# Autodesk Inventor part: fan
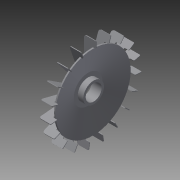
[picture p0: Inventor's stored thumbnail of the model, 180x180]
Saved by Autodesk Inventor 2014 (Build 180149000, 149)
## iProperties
Created: 2002-07
Part Number: fan
Document SubType Name: Modeling
Designer: ales
Density: 1 g/cm^3
Material: Generic
Appearance: Default
Control State: 0
Master: False
Checked Out: False
Shininess: 64.0
Length Units: 11269
Angle Units: 11279
Time Units: 11290
Mass Units: 11283
Length Display Precision: 3
Angle Display Precision: 2
Density: 0.0
Volumn: 0.0
Area: 0.0
PropertySet Name: Model Information
Author: PaulN
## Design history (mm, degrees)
sketch "Sketch1"
  geometry: L1 (0, 0)-(25, 0); L2 (25, 20)-(25, 26); L3 (25, 26)-(11.111, 26); L4 (11.111, 26)-(11.111, 36) reference; L5 (11.111, 36)-(23.519, 94.376); L6 (23.519, 94.376)-(20.585, 95); L7 (8.111, 26)-(0, 26); L8 (0, 26)-(0, 20); L9 (8.111, 26)-(8.111, 36.315); L10 (8.111, 36.315)-(20.585, 95); L11 (0, 20)-(25, 20)
  constraints: 22 end point, 5 perpendicular, 3 parallel, 2 point on line, 1 collinear, 1 horizontal, 1 vertical, 1 other
  dimensions: "d0" = 3 distance between parallel lines of L4 L9; "d1" = 25 distance between parallel lines of L8 L2; "d2" = 10 distance of L3.end L4.end; "d3" = 190 diameter of L6.end L1; "d4" = 3 distance between parallel lines of L5 L10 (= d0); "d5" = 40 diameter of L11 L1; "d6" = 6 distance of L2.start L2.end; "d7" = 12 deg angle of L10 L9
revolve "Revolution1" sketch "Sketch1" stored, may be unused: angle "d8" = 90 deg
sketch "Sketch3"
  geometry: L1 (0, 26)-(8.111, 26) reference; L2 (8.111, 36.315)-(20.585, 95) reference; L3 (8.111, -36.315)-(8.111, 36.315) reference; L4 (1.5, 26)-(1.5, 109); L5 (7.5, 115)-(29.5, 115); L6 (31.5, 113)-(31.5, 100); L7 (29.5, 98)-(22.585, 98); L8 (20.585, 96)-(20.585, 95); L9 (0, -26)-(0, 26) reference; L10 (-6.383, 0)-(38.297, 0) reference; L11 (8.111, 26)-(8.111, 36.315); A1 r 6 centre (7.5, 109) between (7.5, 115) and (1.5, 109); A2 r 2 centre (29.5, 113) between (31.5, 113) and (29.5, 115); A3 r 2 centre (29.5, 100) between (29.5, 98) and (31.5, 100); A4 r 2 centre (22.585, 96) between (22.585, 98) and (20.585, 96); 3 further points
  constraints: 12 end point, 8 point on circle, 8 tangent, 7 point on line, 4 centre point, 4 parallel, 1 collinear, 1 equal radius, 1 perpendicular
  dimensions: "d10" = 1.5 distance between parallel lines of L4 L9; "d11" = 30 distance of point (1.5, 115) point (31.5, 115); "d12" = 17 distance of point (31.5, 115) point (31.5, 98); "d13" = 230 diameter of L5 L10; "d14" = 6 radius of A1; "d15" = 2 radius of A2; "d16" = 2 radius of A4
extrude "Extrusion1" join sketch "Sketch3" stored distance "d17" = 1.5; taper "d18" = 0 deg
body "Solid1"
pattern_circular "Circular Pattern1" dims angle "d21" = 360 deg
